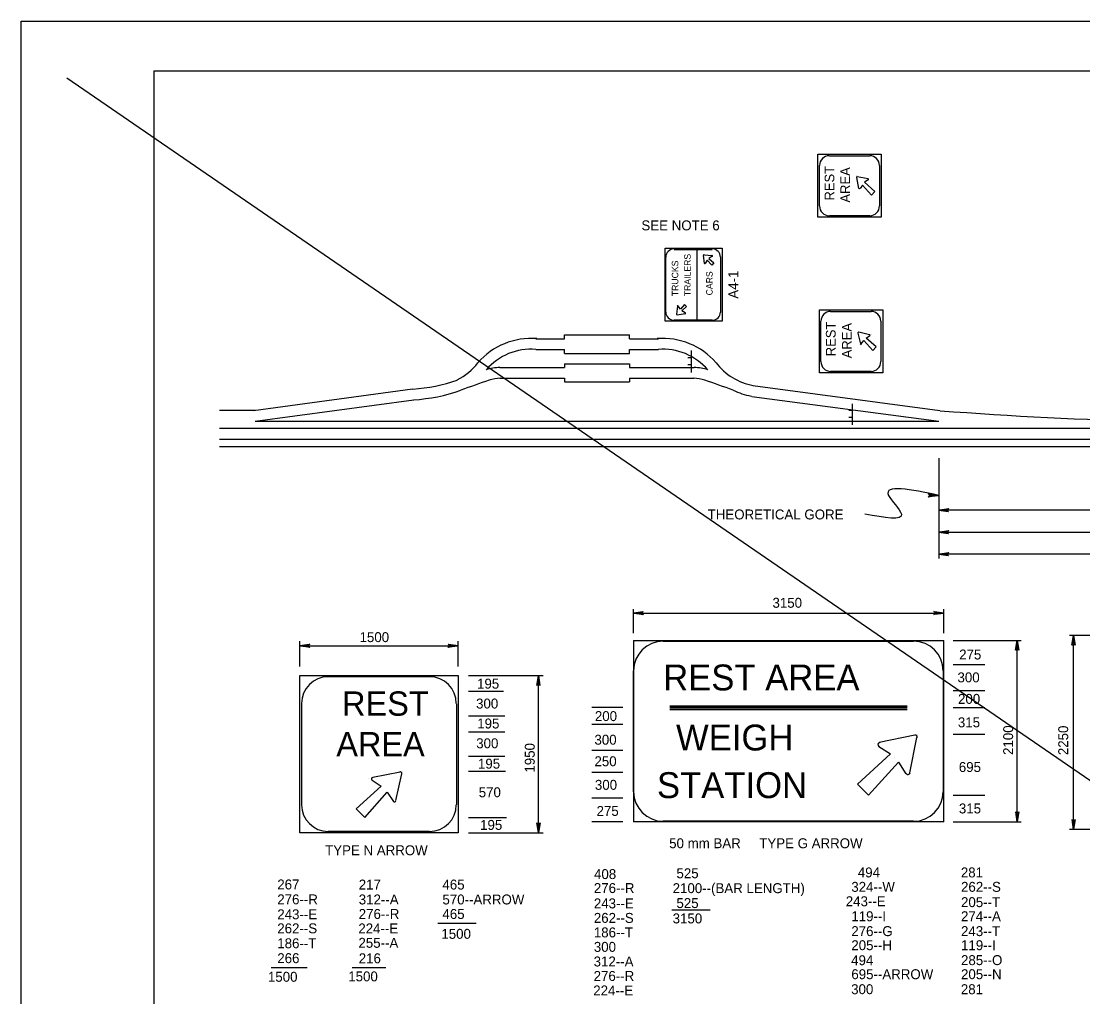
# Model space of a CAD drawing. Extents: x 649604 to 650509, y 298458 to 299646.
# Drawn here: x 649604.3 to 649924.8, y 299351.2 to 299645.6 of the extents above; entities that cross this region are included whole.
import ezdxf

# ---------------------------------------------------------------- set-up
doc = ezdxf.new("R2010")
doc.units = 0
for name, color, linetype in [('1', 7, 'Continuous'), ('2', 7, 'Continuous'), ('3', 7, 'Continuous'), ('PLT-BNDY', 7, 'Continuous')]:
    doc.layers.add(name, color=color, linetype=linetype)

# ---------------------------------------------------------------- blocks, each defined once
blk = doc.blocks.new('RARROW')
at = {"layer": '3'}
blk.add_lwpolyline([(-2.2695, 0.285), (-2.184875, 0.12075), (0, 0), (-2.2695, 0.285), (-2.38575, 0.384625), (0, 0), (-2.183125, -0.108), (-2.262875, -0.2705), (0, 0), (-2.38575, -0.379125), (-2.262875, -0.2705)], dxfattribs=at)

msp = doc.modelspace()

# ---------------------------------------------------------------- linework, layer by layer
at = {"layer": '1'}
for q in [(650430.31, 299630.63), (649644.31, 299066.63)]:
    msp.add_line((649644.31, 299630.63), q, dxfattribs=at)
at = {"layer": '2'}
for p, q in [((649618.13, 299628.5), (650435.92, 299067.1)), ((649848.31, 299605), (649860.56, 299605)), ((649856.56, 299598.75), (649856.56, 299598.75)), ((649857.19, 299595.13), (649856.56, 299598.5)), ((649856.69, 299598.75), (649860.06, 299598.13)), ((649860.06, 299597.75), (649858.94, 299597)), ((649858.31, 299596.13), (649857.56, 299595.13)), ((649861.06, 299593.13), (649858.31, 299596.13)), ((649858.31, 299596.13), (649858.31, 299596.13)), ((649858.94, 299597), (649858.94, 299597)), ((649858.94, 299597), (649862.06, 299594.25)), ((649862.06, 299594.25), (649861.06, 299593.13)), ((649863.94, 299586.5), (649844.81, 299586.5)), ((649860.56, 299586.88), (649848.31, 299586.88)), ((649801.44, 299576.75), (649812.94, 299576.75)), ((649808.44, 299555.5), (649808.44, 299576.75)), ((649810.56, 299575.13), (649812.81, 299574.88)), ((649810.56, 299575), (649810.56, 299575)), ((649810.56, 299572.63), (649810.31, 299574.88)), ((649810.69, 299572.63), (649810.69, 299572.63)), ((649810.69, 299572.38), (649810.69, 299572.38)), ((649810.69, 299572.38), (649810.69, 299572.38)), ((649811.44, 299573.5), (649810.81, 299572.5)), ((649812.81, 299572), (649811.44, 299573.5)), ((649811.44, 299573.5), (649811.44, 299573.5)), ((649811.69, 299573.75), (649811.69, 299573.75)), ((649812.81, 299574.63), (649811.94, 299574)), ((649811.94, 299574), (649811.94, 299574)), ((649811.94, 299574), (649813.44, 299572.75)), ((649812.81, 299574.63), (649812.81, 299574.63)), ((649813.44, 299572.75), (649812.81, 299572)), ((649812.81, 299572), (649812.81, 299572)), ((649812.94, 299574.63), (649812.94, 299574.63)), ((649812.94, 299574.63), (649812.94, 299574.63)), ((649813.44, 299572.75), (649813.44, 299572.75)), ((649802.44, 299559.63), (649802.19, 299557.25)), ((649802.56, 299559.88), (649802.56, 299559.88)), ((649803.31, 299558.75), (649802.69, 299559.63)), ((649804.56, 299560.13), (649803.31, 299558.75)), ((649803.81, 299558.25), (649805.19, 299559.5)), ((649805.19, 299559.5), (649804.56, 299560.13)), ((649802.19, 299557.13), (649802.19, 299557.13)), ((649802.31, 299557), (649804.81, 299557.38)), ((649803.81, 299558.25), (649803.81, 299558.25)), ((649804.81, 299557.63), (649803.81, 299558.25)), ((649804.81, 299557.5), (649804.81, 299557.5)), ((649804.81, 299557.5), (649804.81, 299557.5)), ((649848.69, 299558), (649860.94, 299558)), ((649800.94, 299555.13), (649799.31, 299555.13)), ((649801.44, 299555.5), (649812.94, 299555.5)), ((649808.81, 299555.13), (649807.81, 299555.13)), ((649759.69, 299549.75), (649768.31, 299549.75)), ((649768.31, 299551), (649787.94, 299551)), ((649768.31, 299549.75), (649768.31, 299551)), ((649787.94, 299549.75), (649787.94, 299551)), ((649787.94, 299549.75), (649796.69, 299549.75)), ((649856.81, 299551.75), (649856.81, 299551.75)), ((649856.94, 299551.5), (649857.69, 299548.25)), ((649860.44, 299551), (649857.19, 299551.75)), ((649859.44, 299550), (649860.56, 299550.75)), ((649862.44, 299547.38), (649859.44, 299550)), ((649859.44, 299550), (649859.44, 299550)), ((649860.94, 299551), (649860.94, 299551)), ((649759.69, 299546.5), (649768.31, 299546.5)), ((649768.31, 299545.38), (649768.31, 299546.5)), ((649787.94, 299545.38), (649787.94, 299546.5)), ((649787.94, 299546.5), (649796.69, 299546.5)), ((649806.69, 299539.63), (649806.69, 299546.25)), ((649857.81, 299547.75), (649857.81, 299547.75)), ((649857.94, 299548.25), (649858.69, 299549.25)), ((649858.69, 299549.25), (649858.69, 299549.25)), ((649858.69, 299549.25), (649861.44, 299546.25)), ((649861.44, 299546.25), (649862.44, 299547.38)), ((649768.31, 299545.38), (649787.94, 299545.38)), ((649806.69, 299544), (649805.56, 299544)), ((649748.81, 299541.13), (649768.31, 299541.13)), ((649768.31, 299542.25), (649787.94, 299542.25)), ((649768.31, 299542.25), (649768.31, 299541.13)), ((649787.94, 299542.25), (649787.94, 299541.13)), ((649787.94, 299541.13), (649807.44, 299541.13)), ((649806.69, 299541.88), (649805.56, 299541.88)), ((649860.94, 299539.88), (649848.69, 299539.88)), ((649748.81, 299537.88), (649768.31, 299537.88)), ((649768.31, 299537.88), (649768.31, 299536.75)), ((649768.31, 299536.75), (649787.94, 299536.75)), ((649787.94, 299537.88), (649787.94, 299536.75)), ((649787.94, 299537.88), (649807.44, 299537.88)), ((649864.44, 299539.5), (649845.31, 299539.5)), ((649674.44, 299528.13), (649722.44, 299534.63)), ((649825.19, 299535.63), (649881.69, 299528.13)), ((649674.94, 299524.88), (649722.81, 299531.38)), ((649722.81, 299531.38), (649722.81, 299531.38)), ((649722.81, 299531.38), (649722.81, 299531.38)), ((649824.94, 299532.38), (649824.94, 299532.38)), ((649824.94, 299532.38), (649881.31, 299524.88)), ((649855.31, 299523.75), (649855.31, 299530.13)), ((649674.94, 299528.13), (649664.19, 299528.13)), ((649855.31, 299528.13), (649854.19, 299528.13)), ((649674.94, 299524.88), (649881.31, 299524.88)), ((649674.94, 299524.88), (649674.94, 299524.88)), ((649674.94, 299524.88), (649674.94, 299524.88)), ((649855.31, 299526), (649854.19, 299526)), ((649664.19, 299522.75), (650390.69, 299522.75)), ((649664.19, 299519.5), (650390.69, 299519.5)), ((649664.19, 299517.25), (650390.69, 299517.25)), ((649881.31, 299513.75), (649881.31, 299483.5)), ((650085.69, 299498), (649881.31, 299498)), ((649881.31, 299491.38), (650176.94, 299491.38)), ((650311.69, 299484.75), (649881.31, 299484.75)), ((649789.13, 299460.96), (649789.13, 299468.13)), ((649789.13, 299467), (649882.88, 299467)), ((649882.88, 299460.96), (649882.88, 299468.13)), ((649930.04, 299460.25), (649920.81, 299460.25)), ((649922.06, 299401.63), (649922.06, 299460.25)), ((649688.44, 299450.9), (649688.44, 299458.5)), ((649688.44, 299457.13), (649736.19, 299457.13)), ((649736.19, 299450.9), (649736.19, 299458.5)), ((649789.13, 299458.75), (649882.88, 299458.75)), ((649789.13, 299458.75), (649789.13, 299404)), ((649798.15, 299458.49), (649873.75, 299458.49)), ((649882.88, 299404), (649882.88, 299458.75)), ((649885.67, 299458.75), (649906.17, 299458.75)), ((649905.05, 299404), (649905.05, 299458.75)), ((649885.67, 299451.5), (649895.21, 299451.5)), ((649688.44, 299400.63), (649688.44, 299448.13)), ((649739.4, 299448.13), (649761.94, 299448.13)), ((649760.44, 299400.63), (649760.44, 299448.13)), ((649789.21, 299413.06), (649789.21, 299449.55)), ((649882.7, 299449.55), (649882.7, 299413.06)), ((649885.67, 299443.63), (649895.21, 299443.63)), ((649739.4, 299443.38), (649749.93, 299443.38)), ((649688.94, 299439.63), (649688.94, 299409.13)), ((649735.81, 299409.13), (649735.81, 299439.63)), ((649785.95, 299438.5), (649776.63, 299438.5)), ((649800.13, 299439), (649871.76, 299439)), ((649800.13, 299438.88), (649871.76, 299438.88)), ((649800.13, 299438.5), (649871.76, 299438.5)), ((649800.13, 299438), (649871.76, 299438)), ((649800.13, 299437.88), (649871.76, 299437.88)), ((649885.67, 299438.5), (649895.21, 299438.5)), ((649739.4, 299436), (649750.28, 299436)), ((649739.4, 299431.13), (649750.28, 299431.13)), ((649785.95, 299433.38), (649776.63, 299433.38)), ((649862.01, 299427.63), (649862.01, 299427.63)), ((649874.13, 299430.13), (649863.38, 299427.88)), ((649874.13, 299430.13), (649863.38, 299427.88)), ((649872.63, 299418.75), (649874.76, 299429.38)), ((649872.63, 299418.75), (649874.76, 299429.38)), ((649875.01, 299430.38), (649875.01, 299430.38)), ((649885.67, 299430.38), (649895.21, 299430.38)), ((649785.95, 299425.5), (649776.63, 299425.5)), ((649866.76, 299424.5), (649856.76, 299415.38)), ((649866.76, 299424.5), (649856.76, 299415.38)), ((649863.26, 299426.75), (649866.76, 299424.5)), ((649863.26, 299426.75), (649866.76, 299424.5)), ((649866.76, 299424.5), (649866.76, 299424.5)), ((649739.4, 299423.75), (649750.28, 299423.75)), ((649860.13, 299412), (649869.13, 299422)), ((649860.13, 299412), (649869.13, 299422)), ((649867.88, 299423.25), (649867.88, 299423.25)), ((649869.13, 299422), (649871.38, 299418.5)), ((649869.13, 299422), (649869.13, 299422)), ((649869.13, 299422), (649871.38, 299418.5)), ((649718.69, 299419), (649710.44, 299417.38)), ((649717.44, 299410.38), (649719.19, 299418.5)), ((649719.31, 299419.25), (649719.31, 299419.25)), ((649739.4, 299419.25), (649750.51, 299419.25)), ((649785.95, 299418.88), (649776.63, 299418.88)), ((649712.94, 299414.75), (649705.44, 299407.88)), ((649709.31, 299417.13), (649709.31, 299417.13)), ((649710.31, 299416.5), (649712.94, 299414.75)), ((649712.94, 299414.75), (649712.94, 299414.75)), ((649856.76, 299415.38), (649860.13, 299412)), ((649856.76, 299415.38), (649856.76, 299415.38)), ((649856.76, 299415.38), (649860.13, 299412)), ((649872.38, 299417.25), (649872.38, 299417.25)), ((649708.06, 299405.25), (649714.81, 299412.88)), ((649714.81, 299412.88), (649714.81, 299412.88)), ((649714.81, 299412.88), (649716.69, 299410.13)), ((649860.13, 299412), (649860.13, 299412)), ((649885.67, 299412), (649895.21, 299412)), ((649717.19, 299409.25), (649717.19, 299409.25)), ((649785.95, 299411.13), (649776.63, 299411.13)), ((649705.44, 299407.88), (649708.06, 299405.25)), ((649739.4, 299405.25), (649750.85, 299405.25)), ((649785.95, 299404), (649776.63, 299404)), ((649882.88, 299404), (649789.13, 299404)), ((649873.75, 299404.12), (649798.15, 299404.12)), ((649885.67, 299404), (649906.17, 299404)), ((649739.4, 299400.63), (649761.94, 299400.63)), ((649930.04, 299401.63), (649920.81, 299401.63)), ((649800.7, 299377.45), (649812.29, 299377.45)), ((649730.06, 299373.34), (649741.69, 299373.34)), ((649679.81, 299359.97), (649690.69, 299359.97)), ((649704.19, 299359.97), (649714.44, 299359.97))]:
    msp.add_line(p, q, dxfattribs=at)
for points in [[(649844.81, 299586.5), (649844.81, 299605.5), (649846.81, 299605.5), (649849.81, 299605.5), (649851.69, 299605.5), (649854.56, 299605.5), (649856.56, 299605.5), (649862.19, 299605.5), (649863.94, 299605.5), (649863.94, 299605.5), (649863.94, 299586.5), (649863.94, 299586.5)], [(649845.31, 299589.88), (649845.31, 299602.13)], [(649863.44, 299602.13), (649863.44, 299589.88)], [(649798.69, 299555.13), (649798.69, 299577.13), (649800.31, 299577.13), (649802.19, 299577.13), (649803.69, 299577.13), (649805.69, 299577.13), (649807.06, 299577.13), (649808.56, 299577.13), (649811.81, 299577.13), (649815.94, 299577.13), (649815.94, 299555.13), (649811.19, 299555.13), (649809.31, 299555.13), (649807.06, 299555.13), (649804.69, 299555.13), (649801.44, 299555.13), (649798.69, 299555.13)], [(649798.94, 299557.75), (649798.94, 299574.5)], [(649815.44, 299574.5), (649815.44, 299557.75)], [(649845.31, 299539.5), (649845.31, 299558.5), (649847.31, 299558.5), (649850.19, 299558.5), (649852.06, 299558.5), (649855.06, 299558.5), (649856.81, 299558.5), (649862.56, 299558.5), (649864.44, 299558.5), (649864.44, 299558.5), (649864.44, 299539.5), (649864.44, 299539.5)], [(649845.69, 299542.88), (649845.69, 299555.13)], [(649863.81, 299555.13), (649863.81, 299542.88)], [(649688.44, 299448.13), (649736.19, 299448.13), (649736.19, 299443.38), (649736.19, 299436), (649736.19, 299431.13), (649736.19, 299423.75), (649736.19, 299419.25), (649736.19, 299405.25), (649736.19, 299400.63), (649736.19, 299400.63), (649688.44, 299400.63), (649688.44, 299400.63)], [(649727.56, 299447.75), (649696.94, 299447.75)], [(649696.94, 299401.13), (649727.56, 299401.13)]]:
    msp.add_lwpolyline(points, dxfattribs=at)
for centre, radius, start, end in [((649848.27, 299602.08), 2.93, 90, 180), ((649860.49, 299602.08), 2.93, 0, 90), ((649856.7, 299598.54), 0.183, 78.0958, 191.9043), ((649856.7, 299598.54), 0.183, 78.0958, 191.9043), ((649859.98, 299597.85), 0.183, 302.692, 78.0958), ((649859.98, 299597.85), 0.183, 302.692, 78.0958), ((649857.39, 299595.26), 0.183, 191.9043, 327.308), ((649857.39, 299595.26), 0.183, 191.9042, 327.308), ((649848.27, 299589.86), 2.93, 180, 270), ((649860.49, 299589.86), 2.93, 270, 0), ((649801.36, 299574.44), 2.44, 90, 180), ((649810.44, 299575), 0.153, 84.0498, 185.9502), ((649812.99, 299574.44), 2.44, 0, 90), ((649810.69, 299572.6), 0.153, 185.9502, 328.4461), ((649812.84, 299574.75), 0.153, 301.5539, 84.0498), ((649802.55, 299559.61), 0.153, 31.5539, 174.0498), ((649801.36, 299557.82), 2.44, 180, 270), ((649802.3, 299557.22), 0.153, 174.0498, 275.9502), ((649804.69, 299557.47), 0.153, 275.9502, 58.4461), ((649812.99, 299557.82), 2.44, 270, 0), ((649848.69, 299555.09), 2.93, 90, 180), ((649860.91, 299555.09), 2.93, 0, 90), ((649758.25, 299528.67), 21.21, 85.4134, 139.1043), ((649798.05, 299528.67), 21.21, 40.8957, 94.5866), ((649857.12, 299551.56), 0.183, 78.0958, 191.9043), ((649857.12, 299551.56), 0.183, 78.0958, 191.9043), ((649860.4, 299550.87), 0.183, 302.692, 78.0958), ((649860.4, 299550.87), 0.183, 302.692, 78.0958), ((649758.25, 299528.67), 17.95, 85.4134, 139.1043), ((649798.05, 299528.67), 17.95, 40.8957, 94.5866), ((649857.81, 299548.27), 0.183, 191.9043, 327.308), ((649857.81, 299548.27), 0.183, 191.9043, 327.308), ((649848.69, 299542.87), 2.93, 180, 270), ((649860.91, 299542.87), 2.93, 270, 0), ((649727.53, 299553.9), 18.56, 296.8793, 322.3109), ((649749.74, 299523.33), 17.82, 92.9526, 106.4866), ((649806.56, 299523.33), 17.82, 73.5134, 87.0474), ((649828.77, 299553.9), 18.56, 217.6891, 259.2048), ((649719.77, 299582.56), 48.03, 273.3346, 289.6636), ((651988.02, 293192.03), 6729.85, 109.463364, 109.540836), ((649749.74, 299523.33), 14.56, 92.9526, 106.4866), ((649806.56, 299523.33), 14.56, 73.5134, 87.0474), ((647568.28, 293192.03), 6729.85, 70.459164, 70.536636), ((649719.77, 299582.56), 51.29, 273.3346, 289.6636), ((649828.77, 299553.9), 21.82, 244.1957, 259.2048), ((649975.83, 300763.06), 1238.57, 265.6447, 268.64351), ((649798.15, 299449.55), 8.94, 90, 180), ((649873.75, 299449.55), 8.94, 0, 90), ((649697.03, 299439.68), 8.08, 90, 180), ((649727.58, 299439.68), 8.08, 0, 90), ((649863.63, 299427.28), 0.659, 101.7398, 236.6838), ((649863.63, 299427.28), 0.659, 101.7398, 236.6838), ((649874.21, 299429.48), 0.659, 348.2602, 101.7398), ((649874.21, 299429.48), 0.659, 348.2602, 101.7398), ((649718.74, 299418.62), 0.458, 348.0958, 101.9043), ((649718.74, 299418.62), 0.458, 348.0958, 101.9043), ((649872.01, 299418.9), 0.659, 213.3162, 348.2602), ((649872.01, 299418.9), 0.659, 213.3162, 348.2602), ((649710.53, 299416.89), 0.458, 101.9043, 237.308), ((649710.53, 299416.89), 0.458, 101.9043, 237.308), ((649798.15, 299413.06), 8.94, 180, 270), ((649873.75, 299413.06), 8.94, 270, 0), ((649697.03, 299409.13), 8.08, 180, 270), ((649717.01, 299410.41), 0.458, 212.692, 348.0958), ((649717.01, 299410.41), 0.458, 212.692, 348.0957), ((649727.58, 299409.13), 8.08, 270, 0)]:
    msp.add_arc(centre, radius, start, end, dxfattribs=at)
msp.add_spline([(649881.31, 299502.5), (649866.19, 299502.5), (649870.06, 299496.88), (649859.06, 299496.88)], degree=3, dxfattribs=at)
at = {"layer": 'PLT-BNDY'}
msp.add_lwpolyline([(649604.31, 299645.63), (650445.31, 299645.63), (650445.31, 299051.63), (649604.31, 299051.63)], close=True, dxfattribs=at)

# ---------------------------------------------------------------- block references
at = {"layer": '2', "xscale": 1.2574347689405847, "yscale": 1.3092961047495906}
for p in [(649881.17, 299502.48), (649882.88, 299467), (649736.19, 299457.13)]:
    msp.add_blockref('RARROW', p, dxfattribs=at)
for p, rotation in [((649881.31, 299498), 180), ((649881.31, 299491.38), 180), ((649881.31, 299484.75), 180), ((649789.13, 299467), 180), ((649922.06, 299460.25), 89.99999999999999), ((649688.44, 299457.13), 180), ((649905.05, 299458.75), 89.99999999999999), ((649760.44, 299448.13), 89.99999999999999), ((649905.05, 299404), -90.00000000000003), ((649760.44, 299400.63), -90.00000000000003), ((649922.06, 299401.63), -90.00000000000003)]:
    msp.add_blockref('RARROW', p, dxfattribs=dict(at, rotation=rotation))

# ---------------------------------------------------------------- texts
at = {"layer": '2'}
for s, height, p in [('REST', 2.932, (649849.81, 299591.5)), ('AREA', 2.932, (649854.56, 299590.88)), ('TRAILERS', 1.955, (649806.44, 299562.63)), ('TRUCKS', 1.955, (649802.69, 299562.63)), ('CARS', 1.955, (649813.06, 299562.88)), ('A4-1', 3, (649820.81, 299561.88)), ('REST', 2.932, (649850.19, 299544.5)), ('AREA', 2.932, (649855.06, 299543.88)), ('2100', 3, (649903.79, 299424.16)), ('2250', 3, (649920.41, 299424.09)), ('1950', 3, (649759.35, 299418.82))]:
    msp.add_text(s, height=height, rotation=90, dxfattribs=at).set_placement(p)
for s, height, p in [('SEE NOTE 6', 3, (649791.56, 299582.5)), ('THEORETICAL GORE', 3, (649811.56, 299495.25)), ('3150', 3, (649831.13, 299468.58)), ('1500', 3, (649706.46, 299458.21)), ('275', 3, (649887.49, 299452.97)), ('REST AREA', 7.82, (649798.13, 299443.63)), ('195', 3, (649741.93, 299444.17)), ('300', 3, (649886.99, 299446.07)), ('REST', 7.33, (649701.19, 299436)), ('300', 3, (649741.64, 299438.17)), ('200', 3, (649887.15, 299439.57)), ('200', 3, (649777.51, 299434.38)), ('195', 3, (649741.99, 299432.15)), ('315', 3, (649887.11, 299432.5)), ('AREA', 7.33, (649699.44, 299423.75)), ('WEIGH', 7.82, (649802.01, 299425.5)), ('300', 3, (649741.68, 299426.18)), ('300', 3, (649777.38, 299427.25)), ('195', 3, (649742.21, 299420.02)), ('250', 3, (649777.38, 299420.75)), ('695', 3, (649887.39, 299419)), ('STATION', 7.82, (649796.26, 299411.13)), ('300', 3, (649777.52, 299413.63)), ('570', 3, (649742.44, 299411.39)), ('275', 3, (649778.01, 299405.75)), ('315', 3, (649887.41, 299406.5)), ('195', 3, (649742.86, 299401.53)), ('50 mm BAR     TYPE G ARROW', 3, (649799.94, 299396)), ('TYPE N ARROW', 3, (649696.06, 299393.88)), (' 408   ', 3, (649776.14, 299386.69)), (' 525             ', 3, (649801.02, 299386.94)), ('494      ', 3, (649856.89, 299387.19)), (' 281       ', 3, (649886.89, 299387.19)), ('267   ', 3, (649681.62, 299383.56)), ('217   ', 3, (649706.21, 299383.53)), ('465       ', 3, (649731.48, 299383.53)), (' 324--W    ', 3, (649853.82, 299382.84)), (' 262--S    ', 3, (649886.94, 299382.84)), (' 276--R', 3, (649776.08, 299382.47)), ('2100--(BAR LENGTH)', 3, (649800.99, 299382.44)), ('276--R', 3, (649681.62, 299379.06)), ('312--A', 3, (649706.21, 299379.03)), ('570--ARROW', 3, (649731.48, 299379.03)), (' 243--E', 3, (649776.08, 299377.84)), (' 525             ', 3, (649801.02, 299377.94)), ('  243--E     ', 3, (649851.03, 299378.49)), (' 205--T    ', 3, (649886.94, 299378.22)), ('243--E', 3, (649681.62, 299374.56)), ('276--R', 3, (649706.21, 299374.66)), ('465       ', 3, (649731.48, 299374.65)), (' 262--S', 3, (649776.08, 299373.47)), ('3150             ', 3, (649800.99, 299373.31)), (' 119--I    ', 3, (649853.82, 299373.97)), (' 274--A    ', 3, (649886.94, 299373.97)), ('262--S', 3, (649681.62, 299370.31)), ('224--E', 3, (649706.09, 299370.28)), ('1500        ', 3, (649731.16, 299368.65)), (' 186--T', 3, (649776.08, 299369.09)), (' 276--G    ', 3, (649853.82, 299369.47)), (' 243--T    ', 3, (649886.94, 299369.47)), ('186--T', 3, (649681.62, 299365.81)), ('255--A', 3, (649706.12, 299365.94)), (' 300   ', 3, (649776.08, 299364.72)), (' 205--H    ', 3, (649853.82, 299365.22)), (' 119--I    ', 3, (649886.94, 299365.22)), ('266   ', 3, (649681.62, 299361.31)), ('216   ', 3, (649706.21, 299361.28)), (' 494       ', 3, (649853.77, 299360.69)), (' 285--O    ', 3, (649886.94, 299360.72)), (' 312--A', 3, (649776.02, 299360.31)), ('1500    ', 3, (649678.8, 299355.69)), ('1500    ', 3, (649703.05, 299355.81)), (' 276--R', 3, (649776.02, 299355.94)), (' 695--ARROW', 3, (649853.82, 299356.47)), (' 205--N    ', 3, (649886.94, 299356.47)), (' 224--E', 3, (649775.9, 299351.56)), (' 300       ', 3, (649853.77, 299351.94)), (' 281       ', 3, (649886.89, 299351.94))]:
    msp.add_text(s, height=height, dxfattribs=at).set_placement(p)

doc.saveas('drawing.dxf')
